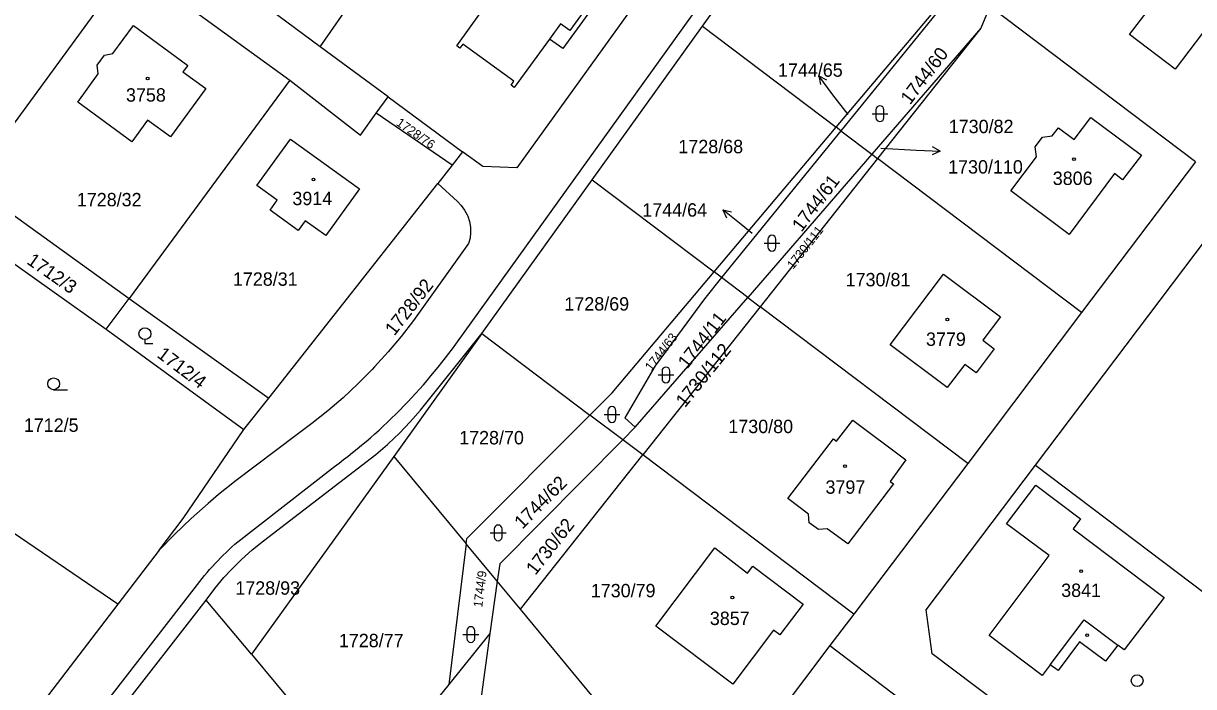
# Model space of a CAD drawing. Extents: x -679220 to -673243, y -1075091 to -1066557.
# Drawn here: x -677162.5 to -677014, y -1072386.3 to -1072302.1 of the extents above; entities that cross this region are included whole.
import ezdxf

# ---------------------------------------------------------------- set-up
doc = ezdxf.new("R2010")
doc.units = 0
for name, color, linetype in [('Hranice parcel', 7, 'Continuous'), ('Parcelní čísla', 7, 'Continuous'), ('Pop  PČ popisy', 7, 'Continuous'), ('Vnitřní kresba', 7, 'Continuous'), ('Značky budov', 7, 'Continuous'), ('Značky kultur', 7, 'Continuous')]:
    doc.layers.add(name, color=color, linetype=linetype)

msp = doc.modelspace()

# ---------------------------------------------------------------- linework, layer by layer
at = {"layer": 'Hranice parcel'}
for p, q in [((-677124.82, -1072305.07), (-677103.85, -1072274.86)), ((-677076.29, -1072302.46), (-677062.3, -1072282.96)), ((-677124.82, -1072305.07), (-677141.95, -1072292.37)), ((-677043.6, -1072297.08), (-677058.73, -1072315.73)), ((-677039.8, -1072299.95), (-677040.98, -1072302.71)), ((-677013.7, -1072319.67), (-677039.8, -1072299.95)), ((-677090.3, -1072321.97), (-677076.29, -1072302.46)), ((-677076.29, -1072302.46), (-677059.34, -1072315.27)), ((-677040.98, -1072302.71), (-677054.81, -1072318.69)), ((-677040.98, -1072302.71), (-677054.07, -1072319.25)), ((-677116.2, -1072311.43), (-677124.82, -1072305.07)), ((-677128.69, -1072309.31), (-677149.08, -1072337.02)), ((-677128.69, -1072309.31), (-677119.71, -1072316.28)), ((-677117.71, -1072313.51), (-677116.2, -1072311.43)), ((-677116.2, -1072311.43), (-677106.75, -1072318.42)), ((-677119.71, -1072316.28), (-677117.71, -1072313.51)), ((-677108.06, -1072320.11), (-677117.71, -1072313.51)), ((-677074.83, -1072333.65), (-677059.34, -1072315.27)), ((-677058.73, -1072315.73), (-677073.86, -1072334.38)), ((-677058.73, -1072315.73), (-677059.34, -1072315.27)), ((-677058.73, -1072315.73), (-677054.81, -1072318.69)), ((-677106.75, -1072318.42), (-677108.06, -1072320.11)), ((-677054.81, -1072318.69), (-677070.55, -1072336.88)), ((-677054.81, -1072318.69), (-677054.07, -1072319.25)), ((-677108.06, -1072320.11), (-677109.88, -1072322.42)), ((-677054.07, -1072319.25), (-677068.98, -1072338.07)), ((-677028.16, -1072338.82), (-677054.07, -1072319.25)), ((-677013.7, -1072319.67), (-677028.16, -1072338.82)), ((-677169.31, -1072322.45), (-677149.08, -1072337.02)), ((-677131.32, -1072349.67), (-677109.88, -1072322.42)), ((-677109.88, -1072322.42), (-677107.41, -1072324.72)), ((-677104.29, -1072341.47), (-677090.3, -1072321.97)), ((-677090.3, -1072321.97), (-677074.83, -1072333.65)), ((-677172.27, -1072326.49), (-677151.99, -1072340.91)), ((-677105.98, -1072330.04), (-677112.99, -1072339.81)), ((-677073.86, -1072334.38), (-677074.83, -1072333.65)), ((-677070.55, -1072336.88), (-677073.86, -1072334.38)), ((-677151.99, -1072340.91), (-677149.08, -1072337.02)), ((-677149.08, -1072337.02), (-677131.32, -1072349.67)), ((-677084.83, -1072353.38), (-677070.55, -1072336.88)), ((-677068.98, -1072338.07), (-677083.88, -1072356.89)), ((-677070.55, -1072336.88), (-677068.98, -1072338.07)), ((-677042.63, -1072357.97), (-677068.98, -1072338.07)), ((-677028.16, -1072338.82), (-677042.63, -1072357.97)), ((-677151.99, -1072340.91), (-677134.51, -1072353.68)), ((-677104.29, -1072341.47), (-677115.49, -1072357.07)), ((-677112.1, -1072351.2), (-677104.29, -1072341.47)), ((-677104.29, -1072341.47), (-677090.58, -1072351.83)), ((-677150.5, -1072375.83), (-677189.16, -1072349.55)), ((-677134.51, -1072353.68), (-677131.32, -1072349.67)), ((-677086.41, -1072354.98), (-677090.58, -1072351.83)), ((-677127.93, -1072354.43), (-677135.47, -1072360.14)), ((-677084.83, -1072353.38), (-677086.41, -1072354.98)), ((-677083.88, -1072356.89), (-677086.41, -1072354.98)), ((-677115.49, -1072357.07), (-677133.56, -1072382.2)), ((-677132.01, -1072367.82), (-677117.77, -1072356.83)), ((-677115.49, -1072357.07), (-677106.28, -1072368.18)), ((-677099.4, -1072376.48), (-677083.88, -1072356.89)), ((-677057.1, -1072377.12), (-677083.88, -1072356.89)), ((-677042.63, -1072357.97), (-677057.1, -1072377.12)), ((-677034.04, -1072358.2), (-677002.92, -1072381.7)), ((-677145.27, -1072368.99), (-677150.5, -1072375.83)), ((-677106.28, -1072368.18), (-677108.5, -1072386.03)), ((-677102.34, -1072372.93), (-677106.28, -1072368.18)), ((-677102.34, -1072372.93), (-677103.27, -1072379.56)), ((-677099.4, -1072376.48), (-677102.34, -1072372.93)), ((-677157.88, -1072399.21), (-677139.3, -1072375.33)), ((-677133.56, -1072382.2), (-677139.3, -1072375.33)), ((-677077.02, -1072403.48), (-677099.4, -1072376.48)), ((-677057.1, -1072377.12), (-677060.11, -1072381.11)), ((-677103.27, -1072379.56), (-677108.5, -1072386.03)), ((-677060.11, -1072381.11), (-677077.02, -1072403.48)), ((-677060.11, -1072381.11), (-677041.76, -1072394.98)), ((-677133.56, -1072382.2), (-677121.78, -1072396.3)), ((-677108.5, -1072386.03), (-677119.32, -1072399.39))]:
    msp.add_line(p, q, dxfattribs=at)
for points in [[(-677097.37, -1072290.93), (-677096.97, -1072291.23), (-677097.3, -1072291.73), (-677090.82, -1072296.45), (-677090.46, -1072295.95), (-677090.06, -1072296.24), (-677090.39, -1072296.74), (-677088.75, -1072297.97), (-677089.04, -1072298.39), (-677094.04, -1072305.28), (-677095.71, -1072304.08), (-677100.19, -1072310.23), (-677100.57, -1072309.94), (-677100.25, -1072309.42), (-677106.73, -1072304.71), (-677107.1, -1072305.22), (-677107.49, -1072304.92), (-677103.08, -1072298.76), (-677108.11, -1072295.09), (-677103.11, -1072288.18), (-677102.82, -1072287.76), (-677097.74, -1072291.44), (-677097.37, -1072290.93)], [(-677079.53, -1072292.18), (-677099.85, -1072320.45), (-677104.18, -1072320.27), (-677106.75, -1072318.42)], [(-677020.75, -1072295.82), (-677016.97, -1072290.85), (-677005.82, -1072299.3), (-677008.29, -1072302.54), (-677010.24, -1072301.07), (-677012.31, -1072303.76), (-677012.83, -1072303.35), (-677016.29, -1072307.91), (-677022.1, -1072303.49), (-677017.91, -1072297.98), (-677020.75, -1072295.82)], [(-677152.92, -1072300.07), (-677150.69, -1072297.02), (-677146.5, -1072296.35), (-677128.69, -1072309.31)], [(-677059.34, -1072315.27), (-677044.95, -1072298.19), (-677044.39, -1072296.48)], [(-677169.31, -1072322.45), (-677153.83, -1072301.4), (-677152.92, -1072300.07)], [(-677152.21, -1072306.14), (-677151.13, -1072305.92), (-677148.51, -1072302.36), (-677141.61, -1072307.43), (-677142.24, -1072308.24), (-677139.33, -1072310.37), (-677143.81, -1072316.51), (-677146.72, -1072314.39), (-677148.71, -1072317.12), (-677155.59, -1072312.1), (-677152.99, -1072308.48), (-677153.11, -1072307.41), (-677152.21, -1072306.14)], [(-677034.04, -1072358.2), (-676999.38, -1072312.31), (-676995.87, -1072311.82), (-676968.74, -1072332.31), (-676968.26, -1072335.81), (-677002.92, -1072381.7)], [(-677031.9, -1072316.36), (-677031.11, -1072315.35), (-677029.12, -1072316.83), (-677027, -1072314.03), (-677020.58, -1072318.82), (-677022.96, -1072321.95), (-677024, -1072321.16), (-677029.75, -1072328.88), (-677037.13, -1072323.35), (-677033.89, -1072319.02), (-677034.07, -1072317.75), (-677033.15, -1072316.55), (-677031.9, -1072316.36)], [(-677119.84, -1072323.11), (-677124.11, -1072329.01), (-677126.71, -1072327.15), (-677127.61, -1072328.38), (-677131.16, -1072325.8), (-677130.27, -1072324.56), (-677132.86, -1072322.69), (-677128.57, -1072316.78), (-677119.84, -1072323.11)], [(-677107.41, -1072324.72), (-677106.92, -1072325.22), (-677106.49, -1072325.79), (-677106.16, -1072326.41), (-677106.08, -1072326.59), (-677105.86, -1072327.26), (-677105.74, -1072327.95), (-677105.72, -1072328.66), (-677105.8, -1072329.36), (-677105.98, -1072330.04)], [(-677090.58, -1072351.83), (-677087.76, -1072349), (-677074.83, -1072333.65)], [(-677073.86, -1072334.38), (-677076.04, -1072337.07), (-677082.31, -1072345.56), (-677086.16, -1072352.2), (-677084.83, -1072353.38)], [(-677045.7, -1072333.93), (-677038.47, -1072339.37), (-677040.7, -1072342.32), (-677039.25, -1072343.41), (-677041.54, -1072346.48), (-677043.01, -1072345.4), (-677045.23, -1072348.34), (-677052.45, -1072342.9), (-677045.7, -1072333.93)], [(-677112.99, -1072339.81), (-677114.56, -1072341.84), (-677116.2, -1072343.81), (-677117.92, -1072345.72), (-677118.23, -1072346.05), (-677120.04, -1072347.88), (-677121.92, -1072349.63), (-677123.86, -1072351.31), (-677125.86, -1072352.91), (-677127.93, -1072354.43)], [(-677117.77, -1072356.83), (-677116.27, -1072355.55), (-677116.19, -1072355.48), (-677114.75, -1072354.12), (-677113.39, -1072352.7), (-677112.1, -1072351.2)], [(-677106.28, -1072368.18), (-677106.2, -1072367.51), (-677090.58, -1072351.83)], [(-677060.46, -1072366.28), (-677061.58, -1072366.35), (-677062.74, -1072365.52), (-677062.84, -1072364.41), (-677065.47, -1072362.41), (-677059.67, -1072354.83), (-677059.28, -1072355.14), (-677057.19, -1072352.47), (-677050.48, -1072357.53), (-677052.48, -1072360.26), (-677052.06, -1072360.58), (-677057.83, -1072368.18), (-677060.46, -1072366.28)], [(-677145.27, -1072368.99), (-677142.21, -1072364.98), (-677134.51, -1072353.68)], [(-677086.41, -1072354.98), (-677102.03, -1072370.7), (-677102.34, -1072372.93)], [(-677002.92, -1072381.7), (-677016.78, -1072400.05), (-677022.38, -1072400.83), (-677047.12, -1072382.15), (-677047.9, -1072376.55), (-677034.04, -1072358.2)], [(-677135.47, -1072360.14), (-677137.72, -1072361.93), (-677139.05, -1072363.05), (-677141.19, -1072364.96), (-677143.27, -1072366.94), (-677145.27, -1072368.99)], [(-677029.24, -1072366.26), (-677017.7, -1072375), (-677022.76, -1072381.65), (-677023.56, -1072381.05), (-677025.13, -1072383.1), (-677028.42, -1072380.62), (-677031.14, -1072384.26), (-677032.14, -1072383.54), (-677033.17, -1072384.9), (-677039.89, -1072379.81), (-677032.3, -1072369.65), (-677037.69, -1072365.66), (-677033.98, -1072360.73), (-677028.29, -1072364.99), (-677029.24, -1072366.26)], [(-677139.3, -1072375.33), (-677138.2, -1072373.86), (-677137.03, -1072372.46), (-677136.12, -1072371.47), (-677134.82, -1072370.18), (-677133.45, -1072368.96), (-677132.01, -1072367.82)], [(-677074.72, -1072368.68), (-677070.59, -1072371.89), (-677069.92, -1072371.03), (-677063.52, -1072375.83), (-677066.48, -1072379.74), (-677067.28, -1072379.14), (-677072.43, -1072386.01), (-677082.22, -1072378.65), (-677074.72, -1072368.68)], [(-677150.5, -1072375.83), (-677162.06, -1072390.97), (-677165.72, -1072395.65)], [(-677103.27, -1072379.56), (-677104.47, -1072388.26), (-677116.27, -1072403.07)]]:
    msp.add_lwpolyline(points, dxfattribs=at)
at = {"layer": 'Pop  PČ popisy'}
for p, q in [((-677059.73, -1072311.16), (-677061.54, -1072308.76)), ((-677061.54, -1072308.76), (-677060.53, -1072309.26)), ((-677061.54, -1072308.76), (-677061.33, -1072309.86)), ((-677057.8, -1072313.68), (-677059.73, -1072311.16)), ((-677053.65, -1072317.95), (-677049.11, -1072318.17)), ((-677049.11, -1072318.17), (-677046.11, -1072318.33)), ((-677046.11, -1072318.33), (-677047.14, -1072318.78)), ((-677046.11, -1072318.33), (-677047.09, -1072317.78)), ((-677071.39, -1072327.65), (-677073.72, -1072325.76)), ((-677073.72, -1072325.76), (-677072.63, -1072326)), ((-677073.72, -1072325.76), (-677073.26, -1072326.78)), ((-677069.99, -1072328.77), (-677071.39, -1072327.65))]:
    msp.add_line(p, q, dxfattribs=at)
at = {"layer": 'Vnitřní kresba'}
for p, q in [((-677089.54, -1072298.04), (-677093.14, -1072302.98)), ((-677094.31, -1072302.14), (-677095.71, -1072304.08)), ((-677093.14, -1072302.98), (-677094.31, -1072302.14)), ((-677135.65, -1072368.24), (-677123.02, -1072358.37)), ((-677032.14, -1072383.54), (-677027.84, -1072377.82)), ((-677027.84, -1072377.82), (-677023.56, -1072381.05))]:
    msp.add_line(p, q, dxfattribs=at)
for points in [[(-677107.61, -1072342.81), (-677072.92, -1072294.47), (-677053.37, -1072267.19), (-677046.38, -1072257.41), (-677043.02, -1072252.23), (-677036.59, -1072242.68)], [(-677123.02, -1072358.37), (-677122.43, -1072357.93), (-677121.85, -1072357.49), (-677121.27, -1072357.04), (-677120.7, -1072356.58), (-677120.13, -1072356.12), (-677119.56, -1072355.65), (-677119, -1072355.18), (-677118.45, -1072354.7), (-677117.9, -1072354.22), (-677117.35, -1072353.73), (-677116.82, -1072353.23), (-677116.28, -1072352.73), (-677115.75, -1072352.22), (-677115.23, -1072351.71), (-677114.71, -1072351.19), (-677114.2, -1072350.67), (-677113.69, -1072350.14), (-677113.19, -1072349.6), (-677112.69, -1072349.06), (-677112.2, -1072348.52), (-677111.71, -1072347.97), (-677111.23, -1072347.42), (-677110.76, -1072346.86), (-677110.29, -1072346.29), (-677109.83, -1072345.73), (-677109.38, -1072345.15), (-677108.92, -1072344.57), (-677108.48, -1072343.99), (-677108.04, -1072343.4), (-677107.61, -1072342.81)], [(-677139.82, -1072372.58), (-677139.5, -1072372.19), (-677139.18, -1072371.81), (-677138.85, -1072371.43), (-677138.51, -1072371.06), (-677138.17, -1072370.69), (-677137.82, -1072370.32), (-677137.47, -1072369.97), (-677137.12, -1072369.61), (-677136.76, -1072369.26), (-677136.39, -1072368.92), (-677136.02, -1072368.57), (-677135.65, -1072368.24)], [(-677174.76, -1072417.75), (-677153.79, -1072390.67), (-677139.82, -1072372.58)]]:
    msp.add_lwpolyline(points, dxfattribs=at)
at = {"layer": 'Značky budov'}
for centre in [(-677146.72, -1072309.08), (-677029.13, -1072319.34), (-677125.67, -1072321.92), (-677045.21, -1072339.7), (-677058.2, -1072358.33), (-677028.23, -1072371.66), (-677072.5, -1072375), (-677027.45, -1072379.77)]:
    msp.add_circle(centre, 0.175, dxfattribs=at)
at = {"layer": 'Značky kultur'}
for p, q in [((-677054.77, -1072313.56), (-677052.77, -1072313.56)), ((-677054.27, -1072313.06), (-677054.27, -1072314.06)), ((-677053.27, -1072314.06), (-677053.27, -1072313.06)), ((-677068.48, -1072330), (-677066.48, -1072330)), ((-677067.98, -1072329.5), (-677067.98, -1072330.5)), ((-677066.98, -1072330.5), (-677066.98, -1072329.5)), ((-677147.07, -1072342.25), (-677147.07, -1072342.75)), ((-677147.07, -1072342.75), (-677146.07, -1072342.75)), ((-677081.93, -1072346.73), (-677079.93, -1072346.73)), ((-677081.43, -1072346.23), (-677081.43, -1072347.23)), ((-677080.43, -1072347.23), (-677080.43, -1072346.23)), ((-677158.66, -1072348.61), (-677156.91, -1072348.61)), ((-677088.29, -1072351.26), (-677088.29, -1072352.26)), ((-677087.29, -1072352.26), (-677087.29, -1072351.26)), ((-677088.79, -1072351.76), (-677086.79, -1072351.76)), ((-677102.73, -1072366.29), (-677102.73, -1072367.29)), ((-677101.73, -1072367.29), (-677101.73, -1072366.29)), ((-677103.23, -1072366.79), (-677101.23, -1072366.79)), ((-677106.7, -1072379.7), (-677104.7, -1072379.7)), ((-677106.2, -1072379.2), (-677106.2, -1072380.2)), ((-677105.2, -1072380.2), (-677105.2, -1072379.2))]:
    msp.add_line(p, q, dxfattribs=at)
for centre in [(-677147.07, -1072341.5), (-677158.66, -1072347.86), (-677021.12, -1072385.56)]:
    msp.add_circle(centre, 0.75, dxfattribs=at)
for centre, start, end in [((-677053.77, -1072313.06), 0, 180), ((-677053.77, -1072314.06), 180, 359.9879), ((-677067.48, -1072329.5), 0, 180), ((-677067.48, -1072330.5), 180, 359.9879), ((-677080.93, -1072346.23), 0, 180), ((-677080.93, -1072347.23), 180, 359.9879), ((-677087.79, -1072351.26), 0, 180), ((-677087.79, -1072352.26), 180, 359.9879), ((-677102.23, -1072366.29), 0, 180), ((-677102.23, -1072367.29), 180, 359.9879), ((-677105.7, -1072379.2), 0, 180), ((-677105.7, -1072380.2), 180, 359.9879)]:
    msp.add_arc(centre, 0.5, start, end, dxfattribs=at)

# ---------------------------------------------------------------- texts
at = {"layer": 'Parcelní čísla'}
for s, height, rotation, p in [('1744/60', 1.7, 53, (-677049.94, -1072312.52)), ('1728/76', 1.139, 325, (-677115.27, -1072314.95)), ('1744/61', 1.7, 53, (-677063.72, -1072328.68)), ('1730/111', 1.14, 52, (-677064.79, -1072333.39)), ('1712/3', 1.7, 325, (-677162.18, -1072332.53)), ('1728/92', 1.7, 52, (-677115.4, -1072341.85)), ('1744/11', 1.7, 52, (-677078.23, -1072346.05)), ('1744/63', 1.14, 52, (-677082.79, -1072346.32)), ('1712/4', 1.7, 323, (-677145.65, -1072344.39)), ('1730/112', 1.7, 51, (-677078.51, -1072350.97)), ('1744/62', 1.7, 45, (-677099.16, -1072366.4)), ('1730/62', 1.7, 52, (-677097.5, -1072372.26)), ('1744/9', 1.14, 83, (-677104.25, -1072376.3))]:
    msp.add_text(s, height=height, rotation=rotation, dxfattribs=at).set_placement(p)
for s, p in [('1744/65', (-677066.71, -1072308.87)), ('3758', (-677149.47, -1072312.03)), ('1730/82', (-677045.03, -1072316.03)), ('1728/68', (-677079.35, -1072318.58)), ('1730/110', (-677045.11, -1072321.16)), ('3806', (-677031.83, -1072322.61)), ('3914', (-677128.35, -1072325.17)), ('1728/32', (-677155.71, -1072325.32)), ('1744/64', (-677083.93, -1072326.63)), ('1728/31', (-677135.9, -1072335.41)), ('1730/81', (-677058.12, -1072335.48)), ('1728/69', (-677093.82, -1072338.56)), ('3779', (-677047.92, -1072343.04)), ('1712/5', (-677162.44, -1072353.96)), ('1730/80', (-677073.01, -1072354.12)), ('1728/70', (-677107.18, -1072355.55)), ('3797', (-677060.68, -1072361.82)), ('1728/93', (-677135.59, -1072374.64)), ('1730/79', (-677090.47, -1072374.97)), ('3841', (-677030.76, -1072374.93)), ('3857', (-677075.36, -1072378.49)), ('1728/77', (-677122.45, -1072381.31))]:
    msp.add_text(s, height=1.7, dxfattribs=at).set_placement(p)

doc.saveas('drawing.dxf')
